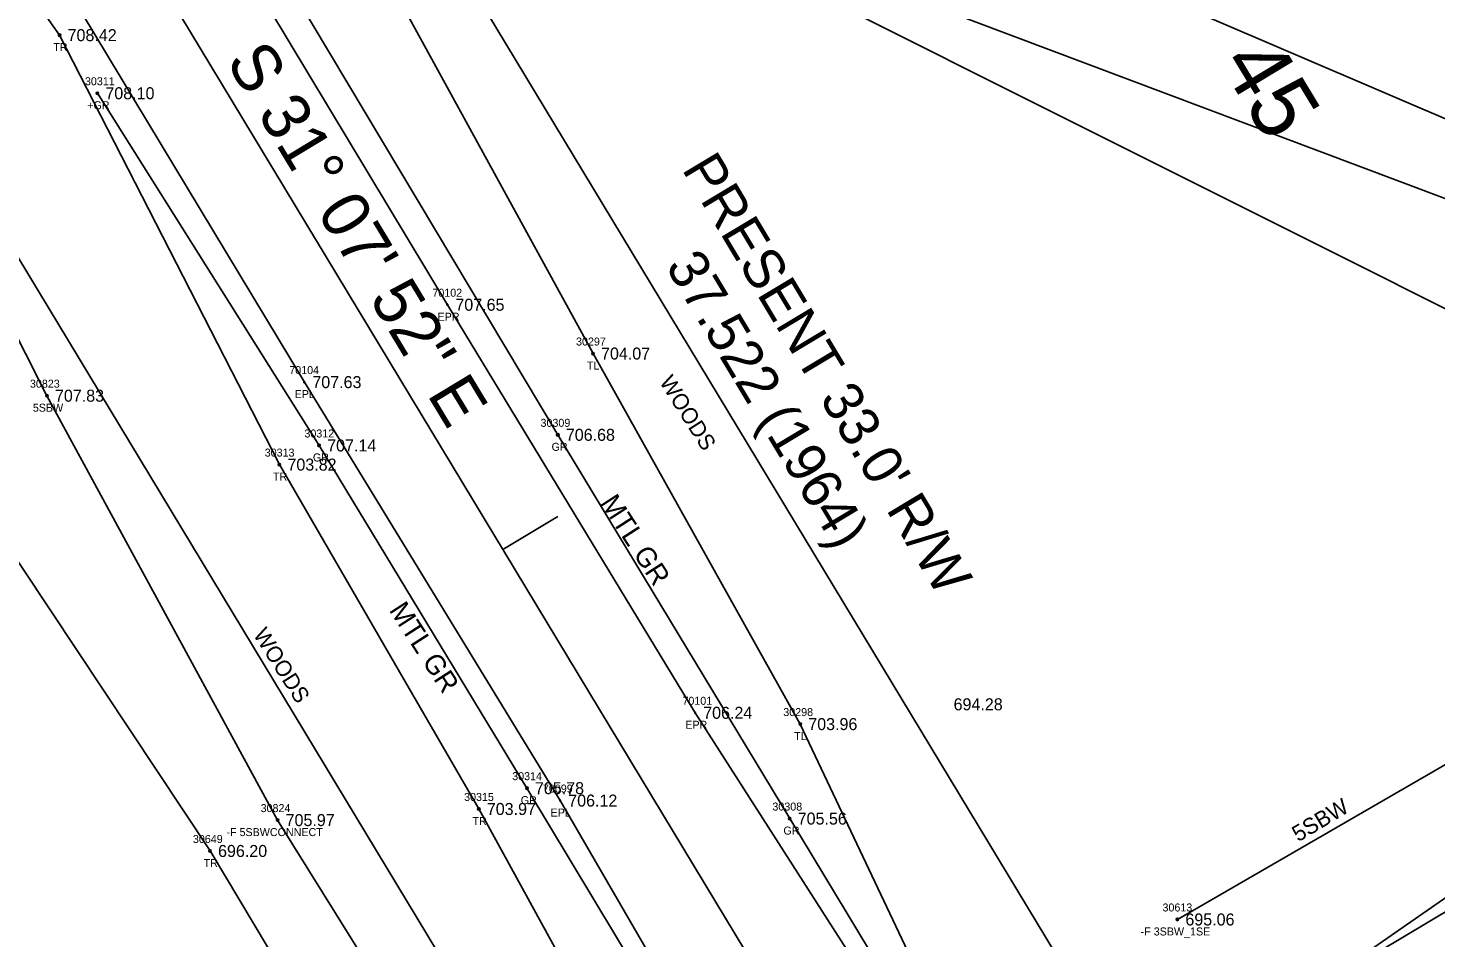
# Model space of a CAD drawing. Extents: x 1375131 to 1378678, y 999028 to 1004053.
# Drawn here: x 1377234.6 to 1377410.5, y 1001730.8 to 1001844.5 of the extents above; entities that cross this region are included whole.
import ezdxf

# ---------------------------------------------------------------- set-up
doc = ezdxf.new("R2010")
doc.units = 0
for name, color, linetype in [('RD_EX_DV_Prop', 7, 'Continuous'), ('RD_EX_DV_TX_Prop(Owner ID)', 7, 'Continuous'), ('RD_EX_Fence_Other', 7, 'Continuous'), ('RD_EX_Fence_Other_txCode', 7, 'Continuous'), ('RD_EX_GuardRail', 7, 'Continuous'), ('RD_EX_GuardRail_txCode', 7, 'Continuous'), ('RD_EX_H2O', 7, 'Continuous'), ('RD_EX_Road', 7, 'Continuous'), ('RD_EX_Road_txCode', 7, 'Continuous'), ('RD_EX_RW', 7, 'Continuous'), ('RD_EX_RW_TX', 7, 'Continuous'), ('RD_EX_SU_Elec', 7, 'Continuous'), ('RD_EX_TX_Fence_Other_ELEV', 7, 'Continuous'), ('RD_EX_TX_GuardRail_ELEV', 7, 'Continuous'), ('RD_EX_TX_Misc_ELEV', 7, 'Continuous'), ('RD_EX_TX_Road_ELEV', 7, 'Continuous'), ('RD_EX_TX_VEG_ELEV', 7, 'Continuous'), ('RD_EX_VEG', 7, 'Continuous'), ('RD_EX_VEG_txCode', 7, 'Continuous'), ('RD_HC_Cl', 7, 'Continuous'), ('RD_HC_Data', 7, 'Continuous'), ('RD_HC_Data_Tic', 7, 'Continuous'), ('RD_HC_TX_Sta50', 7, 'Continuous'), ('RD_SMD_Locator', 7, 'Continuous'), ('RD_TX_Misc1', 7, 'Continuous'), ('RD_TX_Misc2', 7, 'Continuous')]:
    doc.layers.add(name, color=color, linetype=linetype)

msp = doc.modelspace()

# ---------------------------------------------------------------- linework, layer by layer
at = {"layer": 'RD_EX_DV_Prop'}
msp.add_line((1377380.13, 1001713.92), (1377549.86, 1001831.61), dxfattribs=at)
msp.add_lwpolyline([(1377274.73, 1001874.68), (1377493.34, 1001792.42)], dxfattribs=at)
at = {"layer": 'RD_EX_Fence_Other'}
for points in [[(1377637.49, 1002082.79), (1377602.37, 1002057.58), (1377580.56, 1002027.27), (1377564.26, 1001923.93), (1377540.33, 1001858.9), (1377456.19, 1001780.35), (1377421.26, 1001757.98), (1377378.17, 1001733.06)], [(1377191.84, 1001887.9), (1377236.93, 1001798.52), (1377265.75, 1001745.48), (1377304.79, 1001682.79)]]:
    msp.add_lwpolyline(points, dxfattribs=at)
at = {"layer": 'RD_EX_GuardRail'}
for points in [[(1377413.07, 1001610.45), (1377381.61, 1001660.28), (1377356.8, 1001700.83), (1377329.73, 1001745.67), (1377300.76, 1001793.63), (1377267.9, 1001848.65)], [(1377243.23, 1001836.32), (1377270.94, 1001792.3), (1377296.9, 1001749.47), (1377330.01, 1001694.45), (1377359.06, 1001646.8), (1377384.4, 1001604.87), (1377407.06, 1001567.74), (1377414.21, 1001555.7)]]:
    msp.add_lwpolyline(points, dxfattribs=at)
at = {"layer": 'RD_EX_H2O'}
msp.add_lwpolyline([(1377375.48, 1001712.38), (1377425.1, 1001742.05), (1377478.82, 1001780.63), (1377516.49, 1001810.1), (1377555.39, 1001847.34), (1377570.71, 1001887.01), (1377585.15, 1001942.13), (1377603.16, 1001999.03), (1377641.82, 1002043.69), (1377653.81, 1002063.49)], dxfattribs=at)
at = {"layer": 'RD_EX_Road'}
for points in [[(1377350.34, 1001708.26), (1377317.92, 1001758.89), (1377286.96, 1001809.89), (1377254.77, 1001863.4), (1377224.6, 1001914.86), (1377192.26, 1001967.36), (1377160.97, 1002019.84), (1377129.72, 1002070.66), (1377099.39, 1002121.71), (1377064.16, 1002179.08), (1377033.49, 1002231.09), (1377014.7, 1002262.97), (1377013.31, 1002264.91)], [(1377330.92, 1001696.38), (1377301.06, 1001747.92), (1377269.09, 1001800.22), (1377238.03, 1001851.8), (1377206.51, 1001905.09), (1377174.78, 1001956.21), (1377142.24, 1002010.21), (1377112.37, 1002059.86), (1377081.07, 1002112.14), (1377047.75, 1002166.27), (1377015.04, 1002220.7), (1376995.39, 1002252.52), (1376994.75, 1002253.91)]]:
    msp.add_lwpolyline(points, dxfattribs=at)
at = {"layer": 'RD_EX_RW'}
for p, q in [((1377036.35, 1002269.57), (1377580.54, 1001368.57)), ((1376979.85, 1002235.45), (1377524.04, 1001334.45))]:
    msp.add_line(p, q, dxfattribs=at)
at = {"layer": 'RD_EX_SU_Elec'}
msp.add_lwpolyline([(1377174.65, 1001934.87), (1377247.04, 1001903.65), (1377437.44, 1001822.1), (1377567.31, 1002066.68)], dxfattribs=at)
at = {"layer": 'RD_EX_VEG'}
for points in [[(1376925.29, 1002323.56), (1376964.39, 1002271.55), (1376999.6, 1002220.98), (1377033.75, 1002161.52), (1377072.45, 1002098.21), (1377110.65, 1002037.08), (1377148.79, 1001977.33), (1377186.7, 1001917.17), (1377238.51, 1001843.58), (1377265.98, 1001789.91), (1377290.89, 1001746.87), (1377322.19, 1001689.75), (1377357.87, 1001632.38)], [(1377636.58, 1002090.08), (1377595.82, 1002067.58), (1377573.9, 1002031.25), (1377561.3, 1002039.21), (1377460.46, 1001852.08), (1377433.84, 1001798.31), (1377321.3, 1001854.67)], [(1377321.3, 1001854.67), (1377275.03, 1001863.5), (1377273.88, 1001860.91), (1377305.16, 1001803.79), (1377331.05, 1001757.48), (1377351.19, 1001714.88), (1377403.26, 1001649.45), (1377431.16, 1001601.42)], [(1377187.81, 1001646.15), (1377217.03, 1001603.62), (1377308.55, 1001666.34), (1377282.53, 1001699.42), (1377257.31, 1001741.62), (1377227.27, 1001786.89)]]:
    msp.add_lwpolyline(points, dxfattribs=at)
at = {"layer": 'RD_HC_Cl'}
msp.add_line((1377008.1, 1002252.51), (1377552.29, 1001351.51), dxfattribs=at)
at = {"layer": 'RD_HC_Data_Tic'}
msp.add_line((1377293.91, 1001779.3), (1377300.76, 1001783.44), dxfattribs=at)
at = {"layer": 'RD_SMD_Locator'}
for centre, radius in [((1377238.51, 1001843.58), 0.15), ((1377243.23, 1001836.32), 0.15), ((1377286.96, 1001809.89), 0.075), ((1377305.16, 1001803.79), 0.15), ((1377269.09, 1001800.22), 0.075), ((1377236.93, 1001798.52), 0.15), ((1377300.76, 1001793.63), 0.15), ((1377270.94, 1001792.3), 0.15), ((1377265.98, 1001789.91), 0.15), ((1377317.92, 1001758.89), 0.075), ((1377331.05, 1001757.48), 0.15), ((1377296.9, 1001749.47), 0.15), ((1377301.06, 1001747.92), 0.075), ((1377290.89, 1001746.87), 0.15), ((1377265.75, 1001745.48), 0.15), ((1377329.73, 1001745.67), 0.15), ((1377257.31, 1001741.62), 0.15), ((1377378.17, 1001733.06), 0.15)]:
    msp.add_circle(centre, radius, dxfattribs=at)

# ---------------------------------------------------------------- texts
at = {"layer": 'RD_EX_DV_TX_Prop(Owner ID)'}
msp.add_text('INVOLVING PB A99 PG 5, PB P44 PG 564 ', height=5, rotation=336.9202, dxfattribs=at).set_placement((1377310.85, 1001888.92))
at = {"layer": 'RD_EX_Fence_Other_txCode'}
for s, p in [('30823', (1377234.81, 1001799.52)), ('5SBW', (1377235.17, 1001796.52)), ('30824', (1377263.63, 1001746.48)), ('-F 5SBWCONNECT', (1377259.36, 1001743.48)), ('30613', (1377376.31, 1001734.06)), ('-F 3SBW_1SE', (1377373.58, 1001731.06))]:
    msp.add_text(s, height=1, dxfattribs=at).set_placement(p)
at = {"layer": 'RD_EX_GuardRail_txCode'}
for s, p in [('30311', (1377241.68, 1001837.32)), ('+GR', (1377241.97, 1001834.32)), ('30309', (1377298.6, 1001794.63)), ('30312', (1377269.1, 1001793.3)), ('GR', (1377299.98, 1001791.63)), ('GR', (1377270.16, 1001790.3)), ('30314', (1377295.06, 1001750.47)), ('GR', (1377296.12, 1001747.47)), ('30308', (1377327.57, 1001746.67)), ('GR', (1377328.95, 1001743.67))]:
    msp.add_text(s, height=1, dxfattribs=at).set_placement(p)
at = {"layer": 'RD_EX_Road_txCode'}
for s, p in [('70102', (1377285.09, 1001810.89)), ('EPR', (1377285.73, 1001807.89)), ('70104', (1377267.21, 1001801.22)), ('EPL', (1377267.88, 1001798.22)), ('70101', (1377316.33, 1001759.89)), ('EPR', (1377316.69, 1001756.89)), ('70099', (1377298.9, 1001748.92)), ('EPL', (1377299.86, 1001745.92))]:
    msp.add_text(s, height=1, dxfattribs=at).set_placement(p)
at = {"layer": 'RD_EX_RW_TX'}
for s, p in [("PRESENT 33.0' R/W", (1377316.18, 1001826.85)), ('37.522 (1964)', (1377314.14, 1001814.7))]:
    msp.add_text(s, height=5, rotation=300.9801, dxfattribs=at).set_placement(p)
at = {"layer": 'RD_EX_TX_Fence_Other_ELEV'}
for s, p in [('707.83', (1377237.93, 1001797.77)), ('705.97', (1377266.75, 1001744.73)), ('695.06', (1377379.17, 1001732.31))]:
    msp.add_text(s, height=1.5, dxfattribs=at).set_placement(p)
at = {"layer": 'RD_EX_TX_GuardRail_ELEV'}
for s, p in [('708.10', (1377244.23, 1001835.57)), ('706.68', (1377301.76, 1001792.88)), ('707.14', (1377271.94, 1001791.55)), ('705.78', (1377297.9, 1001748.72)), ('705.56', (1377330.73, 1001744.92))]:
    msp.add_text(s, height=1.5, dxfattribs=at).set_placement(p)
at = {"layer": 'RD_EX_TX_Misc_ELEV'}
msp.add_text('694.28', height=1.5, dxfattribs=at).set_placement((1377350.21, 1001759.2))
at = {"layer": 'RD_EX_TX_Road_ELEV'}
for s, p in [('707.65', (1377287.96, 1001809.14)), ('707.63', (1377270.09, 1001799.47)), ('706.24', (1377318.92, 1001758.14)), ('706.12', (1377302.06, 1001747.17))]:
    msp.add_text(s, height=1.5, dxfattribs=at).set_placement(p)
at = {"layer": 'RD_EX_TX_VEG_ELEV'}
for s, p in [('708.42', (1377239.51, 1001842.83)), ('704.07', (1377306.16, 1001803.04)), ('703.82', (1377266.98, 1001789.16)), ('703.96', (1377332.05, 1001756.73)), ('703.97', (1377291.89, 1001746.12)), ('696.20', (1377258.31, 1001740.87))]:
    msp.add_text(s, height=1.5, dxfattribs=at).set_placement(p)
at = {"layer": 'RD_EX_VEG_txCode'}
for s, p in [('TR', (1377237.72, 1001841.58)), ('30297', (1377303.04, 1001804.79)), ('TL', (1377304.39, 1001801.79)), ('30313', (1377264.14, 1001790.91)), ('TR', (1377265.18, 1001787.91)), ('30298', (1377328.93, 1001758.48)), ('TL', (1377330.28, 1001755.48)), ('30315', (1377289.05, 1001747.87)), ('TR', (1377290.09, 1001744.87)), ('30649', (1377255.17, 1001742.62)), ('TR', (1377256.51, 1001739.62))]:
    msp.add_text(s, height=1, dxfattribs=at).set_placement(p)
at = {"layer": 'RD_HC_Data'}
msp.add_text('S 31%%d 07\' 52" E', height=6, rotation=301.1312, dxfattribs=at).set_placement((1377259.21, 1001840.33))
at = {"layer": 'RD_HC_TX_Sta50'}
msp.add_text('45', height=8, rotation=301.1312, dxfattribs=at).set_placement((1377383.38, 1001840.07))
at = {"layer": 'RD_TX_Misc1'}
for p in [(1377305.98, 1001785.14), (1377279.61, 1001771.72)]:
    msp.add_text('MTL GR', height=2.5, rotation=302.8608, dxfattribs=at).set_placement(p)
at = {"layer": 'RD_TX_Misc2'}
for s, rotation, p in [('WOODS', 302.3586, (1377313.38, 1001800.25)), ('WOODS', 302.3586, (1377262.63, 1001768.68)), ('5SBW', 30.804, (1377393.26, 1001742.7))]:
    msp.add_text(s, height=2, rotation=rotation, dxfattribs=at).set_placement(p)

doc.saveas('drawing.dxf')
